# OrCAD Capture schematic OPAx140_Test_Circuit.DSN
size A; title: OPAx140 High-Precision, Low-Noise, Rail-to-Rail Output,; rev: 1.5; note: Datasheet: SBOS498E    EVM: N/A
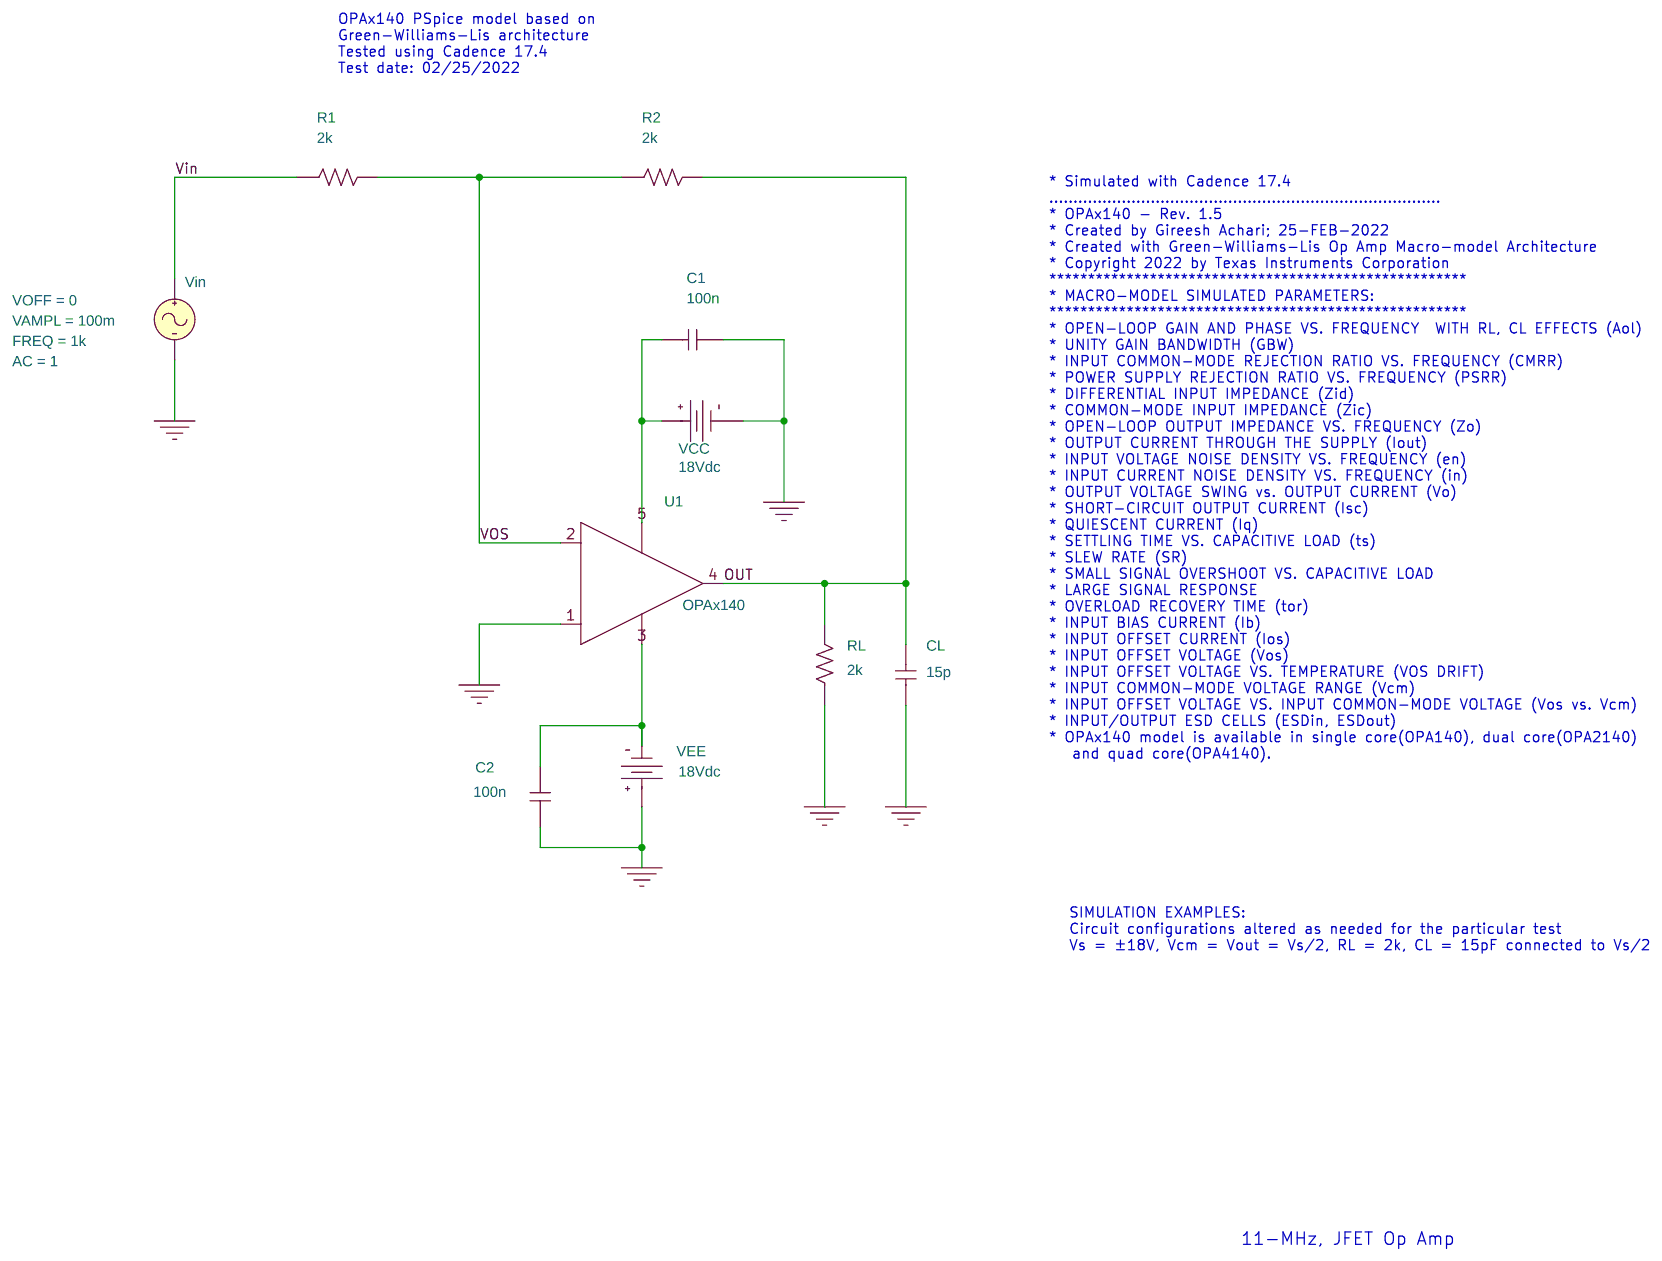
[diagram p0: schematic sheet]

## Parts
C1  100n  [cap196]
C2  100n  [cap196]
CL  15p  [cap196]
R1  2k  [AXRC05]
R2  2k  [AXRC05]
RL  2k  [AXRC05]
U1  OPAx140
VCC  VDC
VEE  VDC
Vin  VSIN

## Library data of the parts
C1 C2 CL = C
R1 R2 RL = R
U1 = OPAx140
VCC VEE = VDC: DC: 18Vdc
Vin = VSIN: AC: 1; FREQ: 1k; VAMPL: 100m; VOFF: 0

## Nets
Vin: R1.1 Vin.1(+)
0: C1.2 C2.1 CL.2 RL.1 U1.1(+) VCC.1(-) VEE.0(+) Vin.2(-)
OUT: CL.1 R2.2 RL.2 U1.4(OUT)
VOS: R1.2 R2.1 U1.2(-)
N27303: C1.1 U1.5(V+) VCC.0(+)
N27354: C2.2 U1.3(V-) VEE.1(-)

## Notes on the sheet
- OPAx140 PSpice model based on
  Green-Williams-Lis architecture
  Tested using Cadence 17.4
  Test date: 02/25/2022
- * Simulated with Cadence 17.4
  .................................................................................
  * OPAx140 - Rev. 1.5
  * Created by Gireesh Achari; 25-FEB-2022
  * Created with Green-Williams-Lis Op Amp Macro-model Architecture
  * Copyright 2022 by Texas Instruments Corporation
  ******************************************************
  * MACRO-MODEL SIMULATED PARAMETERS:
  ******************************************************
  * OPEN-LOOP GAIN AND PHASE VS. FREQUENCY  WITH RL, CL EFFECTS (Aol)
  * UNITY GAIN BANDWIDTH (GBW)
  * INPUT COMMON-MODE REJECTION RATIO VS. FREQUENCY (CMRR)
  * POWER SUPPLY REJECTION RATIO VS. FREQUENCY (PSRR)
  * DIFFERENTIAL INPUT IMPEDANCE (Zid)
  * COMMON-MODE INPUT IMPEDANCE (Zic)
  * OPEN-LOOP OUTPUT IMPEDANCE VS. FREQUENCY (Zo)
  * OUTPUT CURRENT THROUGH THE SUPPLY (Iout)
  * INPUT VOLTAGE NOISE DENSITY VS. FREQUENCY (en)
  * INPUT CURRENT NOISE DENSITY VS. FREQUENCY (in)
  * OUTPUT VOLTAGE SWING vs. OUTPUT CURRENT (Vo)
  * SHORT-CIRCUIT OUTPUT CURRENT (Isc)
  * QUIESCENT CURRENT (Iq)
  * SETTLING TIME VS. CAPACITIVE LOAD (ts)
  * SLEW RATE (SR)
  * SMALL SIGNAL OVERSHOOT VS. CAPACITIVE LOAD
  * LARGE SIGNAL RESPONSE
  * OVERLOAD RECOVERY TIME (tor)
  * INPUT BIAS CURRENT (Ib)
  * INPUT OFFSET CURRENT (Ios)
  * INPUT OFFSET VOLTAGE (Vos)
  * INPUT OFFSET VOLTAGE VS. TEMPERATURE (VOS DRIFT)
  * INPUT COMMON-MODE VOLTAGE RANGE (Vcm)
  * INPUT OFFSET VOLTAGE VS. INPUT COMMON-MODE VOLTAGE (Vos vs. Vcm)
  * INPUT/OUTPUT ESD CELLS (ESDin, ESDout)
  * OPAx140 model is available in single core(OPA140), dual core(OPA2140)
     and quad core(OPA4140).
- SIMULATION EXAMPLES:
  Circuit configurations altered as needed for the particular test
  Vs = ±18V, Vcm = Vout = Vs/2, RL = 2k, CL = 15pF connected to Vs/2
- 11-MHz, JFET Op Amp
